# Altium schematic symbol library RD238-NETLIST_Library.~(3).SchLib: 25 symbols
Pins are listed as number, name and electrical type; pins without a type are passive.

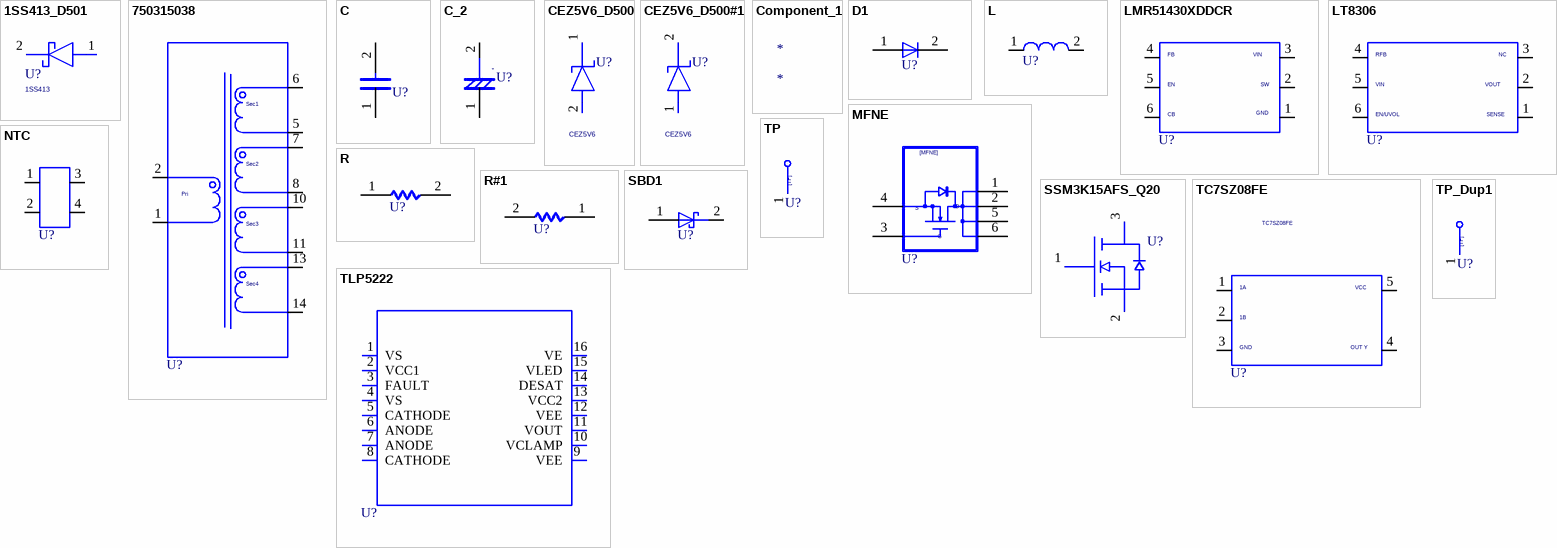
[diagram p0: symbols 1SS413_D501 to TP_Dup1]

## 1SS413_D501
designator U?, comment 1SS413
MANUFACTURER: toshiba; ORDER: $pOrder; COMP: 1SS413_D501; 特性1: 20V; 特性2: 50mA; DESCRIPTION-A: Schottky Barrier Diode, 20V, 50mA; TIME: 08:52:39; UPDATEUSER: sptcae13; SAVECOUNT: 1; OriginalSymbolOrigin: (2540,0); Altium-Right: 50; Altium-Bottom: 20
pins: 1 ANODE, 2 CATHODE

## 750315038
designator U?  (value not drawn)
SAVECOUNT: 24; SAVEAREA0: -14227,-538,38802,29317; TIME: 11:19:06; UPDATEUSER: t5459927; UPDATETIME: 08:42:27; OriginalSymbolOrigin: (2540,55880); Altium-Right: 80; Altium-Bottom: 210
pins: 1, 2, 5, 6, 7, 8, 10, 11, 13, 14

## C
designator U?  (value not drawn)
OriginalSymbolOrigin: (2540,7620); Altium-Right: 20; Altium-Bottom: 10
pins: 1, 2

## C_2
designator U?  (value not drawn)
TIME: 11:26:26; UPDATEUSER: sptcae09; SAVECOUNT: 1; OriginalSymbolOrigin: (2540,10160); Altium-Right: 20
pins: 1, 2

## CEZ5V6_D500
designator U?, comment CEZ5V6
MANUFACTURER: toshiba; ORDER: $pOrder; COMP: CEZ5V6_D500; 特性1: 5.6V; 特性2: 5mA; DESCRIPTION-A: DIODE Zener, 5.6V, 5mA, 150mW; TIME: 08:52:39; UPDATEUSER: sptcae13; SAVECOUNT: 1; OriginalSymbolOrigin: (0,-2540); Altium-Right: 20; Altium-Bottom: 50
pins: 1 CATHODE, 2 ANODE

## CEZ5V6_D500#1
designator U?, comment CEZ5V6
MANUFACTURER: toshiba; ORDER: $pOrder; COMP: CEZ5V6_D500; 特性1: 5.6V; 特性2: 5mA; DESCRIPTION-A: DIODE Zener, 5.6V, 5mA, 150mW; TIME: 08:52:39; UPDATEUSER: sptcae13; SAVECOUNT: 1; OriginalSymbolOrigin: (0,-2540); Altium-Right: 20; Altium-Bottom: 50
pins: 1 ANODE, 2 CATHODE

## Component_1
designator *

## D1
designator U?  (value not drawn)
SAVEAREA0: -225,-91,12804,7836; SAVECOUNT: 4; TIME: 14:49:55; UPDATEUSER: w20165dm; UPDATETIME: 14:35:38; OriginalSymbolOrigin: (5080,5080); Altium-Right: 10; Altium-Bottom: 20
pins: 1, 2

## L
designator U?  (value not drawn)
SAVECOUNT: 24; SAVEAREA0: -14227,-538,38802,29317; TIME: 11:19:06; UPDATEUSER: sptcae09; UPDATETIME: 15:04:42; COMP: 750315038; OriginalSymbolOrigin: (2540,5080); Altium-Right: 30; Altium-Bottom: 20
pins: 1, 2

## LMR51430XDDCR
designator U?, comment TCR1HF50B  (value not drawn)
MANUFACTURER: toshiba; ORDER: $pOrder; 特性1: 36 V; 特性2: 150mA; DESCRIPTION-A: LDO; TIME: 08:52:33; UPDATEUSER: sptcae09; UPDATETIME: 14:43:51; SAVECOUNT: 8; COMPONENTNAME: LMR51430XDDCR; OriginalSymbolOrigin: (2540,17780); Altium-Right: 80; Altium-Bottom: 60
pins: 1, 2, 3, 4, 5, 6

## LT8306
designator U?, comment TCR1HF50B  (value not drawn)
MANUFACTURER: toshiba; ORDER: $pOrder; 特性1: 36 V; 特性2: 150mA; DESCRIPTION-A: LDO; TIME: 08:52:33; UPDATEUSER: sptcae09; UPDATETIME: 10:47:12; SAVECOUNT: 7; COMPONENTNAME: LT8306; OriginalSymbolOrigin: (2540,17780); Altium-Right: 100; Altium-Bottom: 60
pins: 1, 2, 3, 4, 5, 6

## MFNE
designator U?  (value not drawn)
SAVECOUNT: 14; SAVEAREA0: -7120,-295,29516,23636; OriginalSymbolOrigin: (5080,20320); Altium-Right: 50; Altium-Bottom: 70
pins: 1, 2, 3, 4, 5, 6

## NTC
designator U?, comment TCR1HF50B  (value not drawn)
MANUFACTURER: toshiba; ORDER: $pOrder; 特性1: 36 V; 特性2: 150mA; DESCRIPTION-A: LDO; TIME: 08:52:33; UPDATEUSER: sptcae09; UPDATETIME: 07:55:13; SAVECOUNT: 8; COMPONENTNAME: LT8306; OriginalSymbolOrigin: (5080,12700); Altium-Right: 20; Altium-Bottom: 40
pins: 1, 2, 3, 4

## R
designator U?  (value not drawn)
OriginalSymbolOrigin: (5080,5080); Altium-Right: 20
pins: 1, 2

## R#1
designator U?, comment R  (value not drawn)
OriginalSymbolOrigin: (5080,5080); Altium-Right: 20
pins: 1 2, 2 1

## SBD1
designator U?  (value not drawn)
SAVEAREA0: -4630,-153,17114,13055; TIME: 14:49:55; UPDATEUSER: w20165dm; UPDATETIME: 13:53:59; SAVECOUNT: 10; OriginalSymbolOrigin: (5080,5080); Altium-Right: 20
pins: 1, 2

## SSM3K15AFS_Q20
designator U?, comment SSM3K318R  (value not drawn)
MANUFACTURER: toshiba; ORDER: $pOrder; COMP: SSM3K15AFS_Q20; 特性1: 60V; 特性2: 2.5A; 特性3: RON; DESCRIPTION-A: Nch-MOSFET, 60V, 2.5A; TIME: 08:52:39; UPDATEUSER: sptcae09; UPDATETIME: 15:47:00; SAVECOUNT: 8; OriginalSymbolOrigin: (0,-2540); Altium-Right: 60; Altium-Bottom: 70
pins: 1 G, 2 S, 3 D

## TC7SZ08FE
designator U?, comment COMP: TC7SZ08FE  (hidden comment: TCR1HF50B)
MANUFACTURER: toshiba; ORDER: $pOrder; 特性1: 36 V; 特性2: 150mA; DESCRIPTION-A: LDO; TIME: 08:52:33; UPDATEUSER: sptcae09; UPDATETIME: 15:19:01; SAVECOUNT: 9; OriginalSymbolOrigin: (2540,17780); Altium-Right: 100; Altium-Bottom: 60
pins: 1, 2, 3, 4, 5

## TLP5222
designator U?, comment TLP5231  (value not drawn)
MANUFACTURER: toshiba; ORDER: $pOrder; COMP: TLP5222; 特性1: 7 V,35 V; 特性2: 2.5A; DESCRIPTION-A: Gate Driver; TIME: 08:52:32; UPDATEUSER: sptcae09; UPDATETIME: 15:58:41; SAVECOUNT: 8; OriginalSymbolOrigin: (0,-22860); Altium-Right: 150; Altium-Bottom: 130
pins: 1 VS, 2 VCC1, 3 FAULT, 4 VS, 5 CATHODE, 6 ANODE, 7 ANODE, 8 CATHODE, 9 VEE, 10 VCLAMP, 11 VOUT, 12 VEE, 13 VCC2, 14 DESAT, 15 VLED, 16 VE

## TP
designator U?  (value not drawn)
TIME: 16:12:21; UPDATEUSER: fukuda-y; UPDATETIME: 16:18:11; SAVECOUNT: 2; SAVEAREA0: -242,-92,12810,7836; OriginalSymbolOrigin: (0,7620); Altium-Right: 20; Altium-Bottom: 30
pins: 1

## TP_Dup1
designator U?, comment TP  (value not drawn)
TIME: 16:12:21; UPDATEUSER: fukuda-y; UPDATETIME: 16:18:11; SAVECOUNT: 2; SAVEAREA0: -242,-92,12810,7836; OriginalSymbolOrigin: (0,7620); Altium-Right: 20; Altium-Bottom: 30
pins: 1

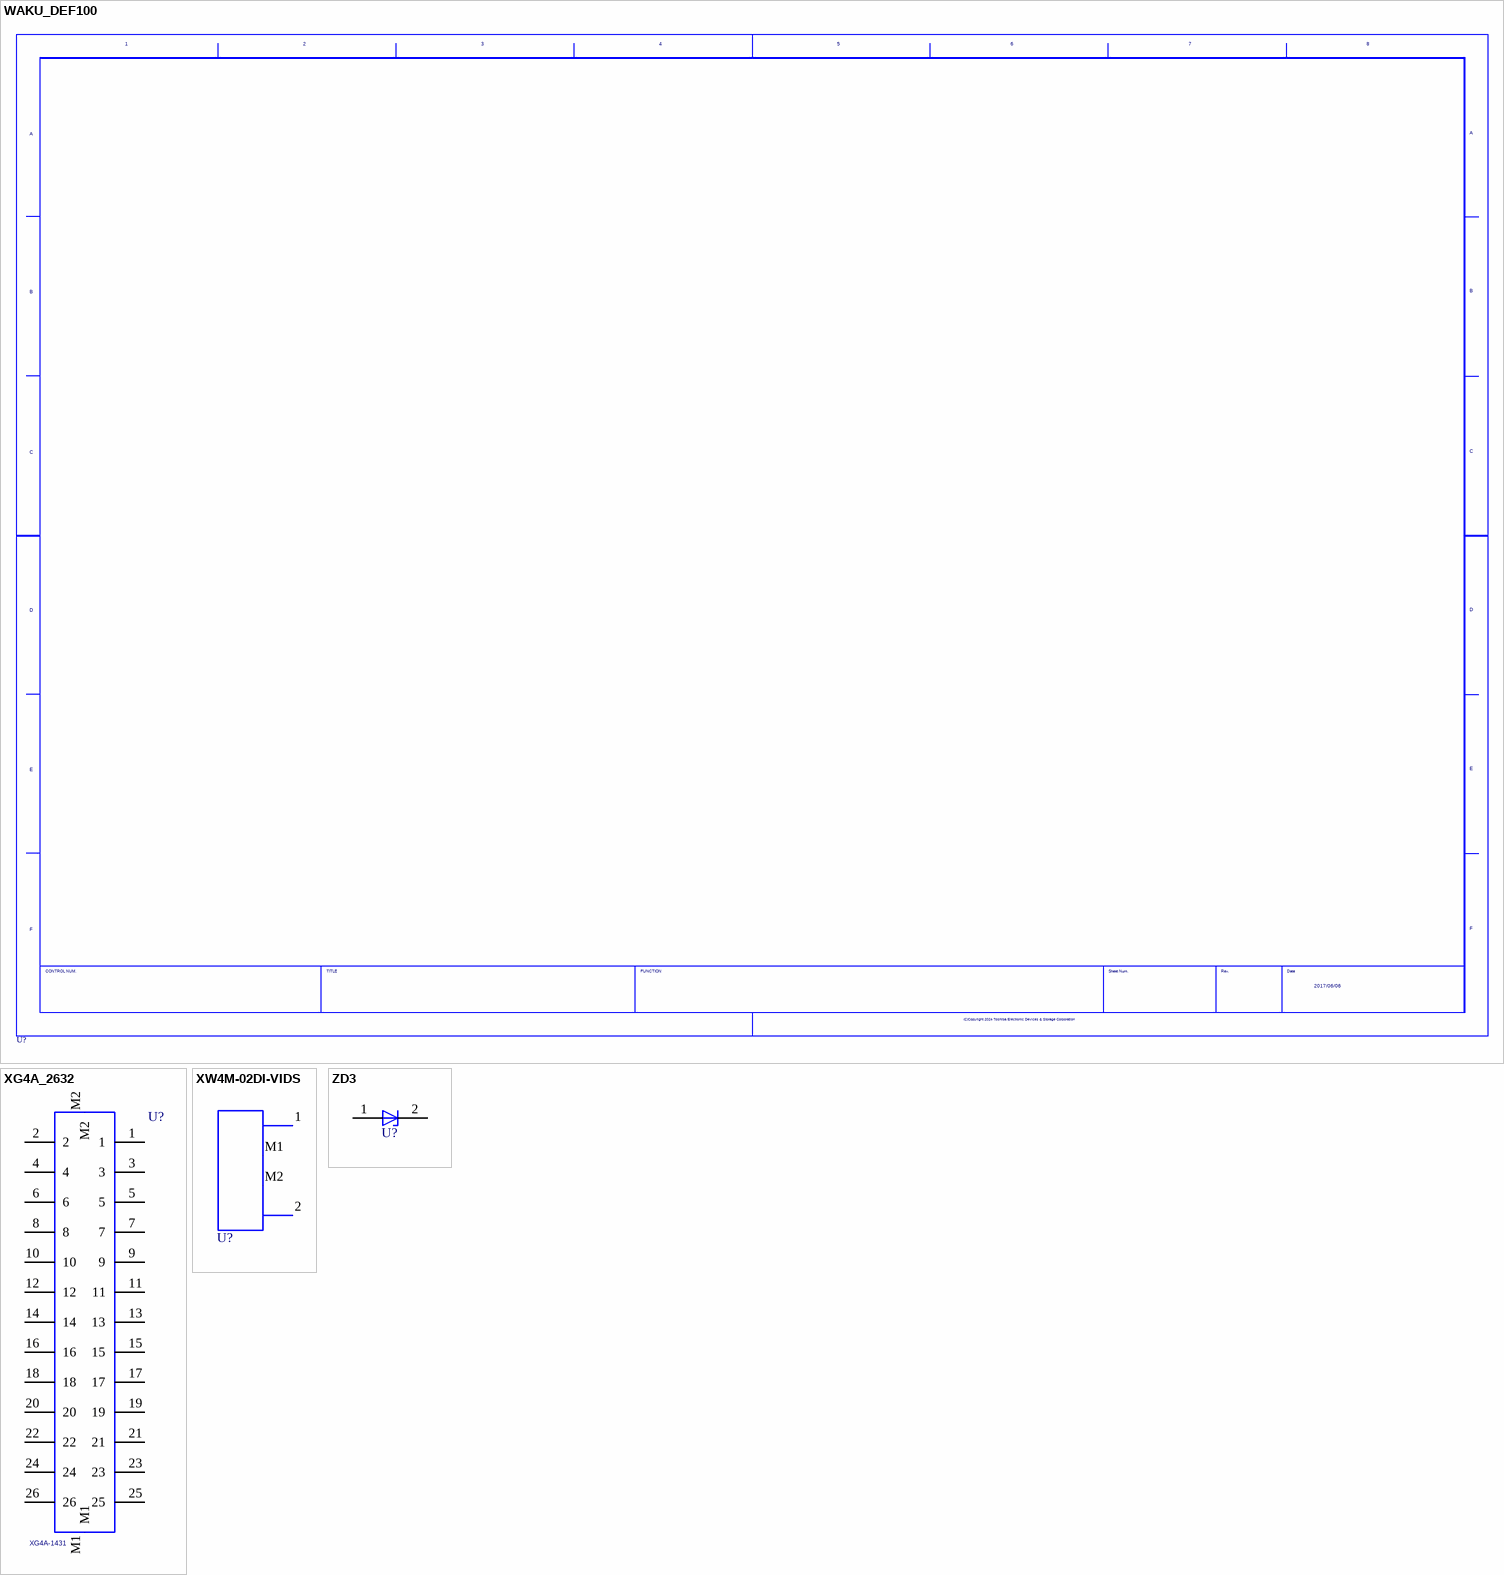
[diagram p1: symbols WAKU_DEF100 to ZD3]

## WAKU_DEF100
designator U?  DATE: 2017/06/06  (hidden comment: WAKU_DEF100)
PLOTTIME: HH:MM; SAVEAREA0: 185750,-43960,448537,75779; TIME: 14:30:25; UPDATEUSER: t5459927; UPDATETIME: 19:15:00; SAVECOUNT: 9; OriginalSymbolOrigin: (10160,284480); Altium-Right: 1570; Altium-Bottom: 1070

## XG4A_2632
designator U?, comment XG4A-1431
MANUFACTURER: OMRON; ORDER: $pOrder; COMP: XG4A-1431, 14PIN, 2列_CN1; 特性1: 300V, 3A; 特性2: 14端子, 2列 x 7端子; DESCRIPTION-A: XG4A MIL Plugs with Long Locks (MIL Standards); TIME: 08:52:43; UPDATEUSER: t5459927; UPDATETIME: 14:58:17; SAVECOUNT: 9; OriginalSymbolOrigin: (5080,0); Altium-Right: 40; Altium-Bottom: 280
pins: 1, 2, 3, 4, 5, 6, 7, 8, 9, 10, 11, 12, 13, 14, 15, 16, 17, 18, 19, 20, 21, 22, 23, 24, 25, 26, M1, M2

## XW4M-02DI-VIDS
designator U?  (value not drawn)
SAVECOUNT: 28; SAVEAREA0: -772,-286,43980,28213; TIME: 16:55:50; UPDATEUSER: t5459927; UPDATETIME: 14:55:33; OriginalSymbolOrigin: (2540,22860); Altium-Right: 50; Altium-Bottom: 80
pins: 1, 2, M1 empty-1, M2 empty-2

## ZD3
designator U?  (value not drawn)
SAVEAREA0: -4630,-153,17114,13055; TIME: 14:49:55; UPDATEUSER: w20165dm; UPDATETIME: 14:57:31; SAVECOUNT: 8; OriginalSymbolOrigin: (5080,5080); Altium-Right: 10; Altium-Bottom: 20
pins: 1 2, 2 1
